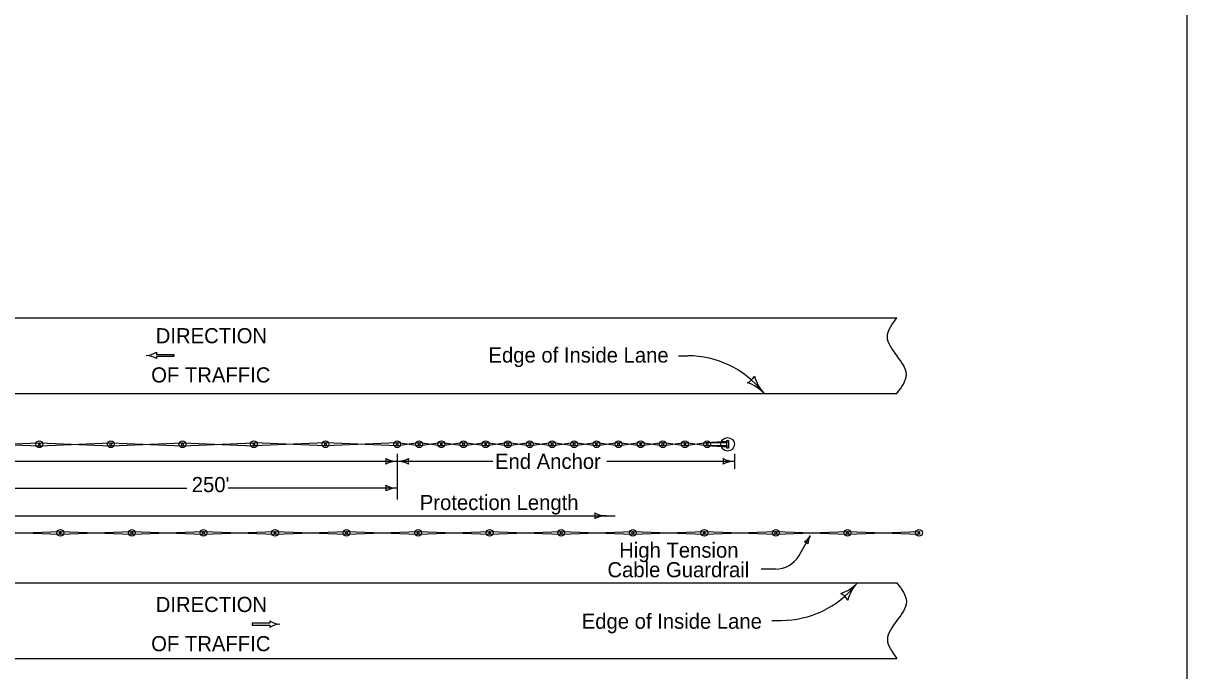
# Model space of a CAD drawing. Extents: x 10133 to 81668, y 7924 to 11018.
# Drawn here: x 12346 to 13268, y 8918 to 9431 of the extents above; entities that cross this region are included whole.
import ezdxf

# ---------------------------------------------------------------- set-up
doc = ezdxf.new("R2010")
doc.units = 0
for name, color, linetype in [('dsnCellElements', 7, 'Continuous'), ('DsnShtRevisedText', 7, 'Continuous'), ('dsnStdDimension', 7, 'Continuous'), ('SheetBorder', 7, 'Continuous')]:
    doc.layers.add(name, color=color, linetype=linetype)

msp = doc.modelspace()

# ---------------------------------------------------------------- linework, layer by layer
at = {"layer": 'dsnCellElements'}
for p, q in [((12302.05, 9098.14), (12357.82, 9095.89)), ((12302.05, 9095.89), (12357.82, 9098.14)), ((12358.76, 9098.14), (12414.52, 9095.89)), ((12358.76, 9095.89), (12414.52, 9098.14)), ((12415.46, 9098.14), (12471.22, 9095.89)), ((12415.46, 9095.89), (12471.22, 9098.14)), ((12472.16, 9098.14), (12527.92, 9095.89)), ((12472.16, 9095.89), (12527.92, 9098.14)), ((12584.62, 9095.89), (12528.86, 9098.14)), ((12584.62, 9098.14), (12528.86, 9095.89)), ((12641.32, 9095.89), (12585.56, 9098.14)), ((12641.32, 9098.14), (12585.56, 9095.89)), ((12658.89, 9095.88), (12642.26, 9098.14)), ((12658.89, 9098.14), (12642.26, 9095.89)), ((12676.41, 9095.89), (12659.83, 9098.14)), ((12676.41, 9098.14), (12659.83, 9095.88)), ((12693.98, 9095.89), (12677.35, 9098.14)), ((12693.98, 9098.14), (12677.35, 9095.89)), ((12711.5, 9095.89), (12694.92, 9098.14)), ((12711.5, 9098.14), (12694.92, 9095.89)), ((12729.07, 9095.89), (12712.44, 9098.14)), ((12729.07, 9098.14), (12712.44, 9095.89)), ((12746.59, 9095.89), (12730.01, 9098.14)), ((12746.59, 9098.14), (12730.01, 9095.89)), ((12764.16, 9095.89), (12747.53, 9098.14)), ((12764.16, 9098.14), (12747.53, 9095.89)), ((12781.68, 9098.14), (12765.1, 9095.89)), ((12781.68, 9095.89), (12765.1, 9098.14)), ((12799.25, 9095.89), (12782.62, 9098.14)), ((12799.25, 9098.14), (12782.62, 9095.89)), ((12816.77, 9095.89), (12800.19, 9098.14)), ((12816.77, 9098.14), (12800.19, 9095.89)), ((12834.35, 9095.89), (12817.72, 9098.14)), ((12834.35, 9098.14), (12817.72, 9095.89)), ((12851.88, 9095.89), (12835.29, 9098.14)), ((12851.88, 9098.14), (12835.29, 9095.89)), ((12869.46, 9095.89), (12852.82, 9098.14)), ((12869.46, 9098.14), (12852.82, 9095.89)), ((12886.98, 9095.89), (12870.39, 9098.14)), ((12886.98, 9098.14), (12870.39, 9095.89)), ((12903.74, 9099.32), (12886.98, 9098.14)), ((12903.74, 9094.71), (12886.98, 9095.89)), ((12903.74, 9098.14), (12887.91, 9098.14)), ((12903.74, 9095.89), (12887.91, 9095.89)), ((12318.73, 9027.97), (12374.49, 9025.72)), ((12318.73, 9025.72), (12374.49, 9027.97)), ((12375.43, 9027.97), (12431.19, 9025.72)), ((12375.43, 9025.72), (12431.19, 9027.97)), ((12432.13, 9027.97), (12487.89, 9025.72)), ((12432.13, 9025.72), (12487.89, 9027.97)), ((12488.83, 9027.97), (12544.59, 9025.72)), ((12488.83, 9025.72), (12544.59, 9027.97)), ((12545.53, 9027.97), (12601.29, 9025.72)), ((12545.53, 9025.72), (12601.29, 9027.97)), ((12602.23, 9027.97), (12658, 9025.72)), ((12602.23, 9025.72), (12658, 9027.97)), ((12658.93, 9027.97), (12714.7, 9025.72)), ((12658.93, 9025.72), (12714.7, 9027.97)), ((12715.64, 9027.97), (12771.4, 9025.72)), ((12715.64, 9025.72), (12771.4, 9027.97)), ((12772.34, 9027.97), (12828.1, 9025.72)), ((12772.34, 9025.72), (12828.1, 9027.97)), ((12829.04, 9027.97), (12884.8, 9025.72)), ((12829.04, 9025.72), (12884.8, 9027.97)), ((12885.74, 9027.97), (12941.5, 9025.72)), ((12885.74, 9025.72), (12941.5, 9027.97)), ((12942.44, 9027.97), (12998.2, 9025.72)), ((12942.44, 9025.72), (12998.2, 9027.97)), ((12999.14, 9027.97), (13054.9, 9025.72)), ((12999.14, 9025.72), (13054.9, 9027.97))]:
    msp.add_line(p, q, dxfattribs=at)
for points in [[(12904.34, 9100.02), (12904.34, 9094.01), (12903.13, 9094.01), (12903.13, 9100.02)], [(12357.82, 9095.89), (12357.82, 9098.14), (12358.76, 9098.14), (12358.76, 9095.89)], [(12357.82, 9095.89), (12357.82, 9098.14), (12358.76, 9098.14), (12358.76, 9095.89)], [(12414.52, 9095.89), (12414.52, 9098.14), (12415.46, 9098.14), (12415.46, 9095.89)], [(12414.52, 9095.89), (12414.52, 9098.14), (12415.46, 9098.14), (12415.46, 9095.89)], [(12471.22, 9095.89), (12471.22, 9098.14), (12472.16, 9098.14), (12472.16, 9095.89)], [(12471.22, 9095.89), (12471.22, 9098.14), (12472.16, 9098.14), (12472.16, 9095.89)], [(12528.86, 9098.14), (12528.86, 9095.89), (12527.92, 9095.89), (12527.92, 9098.14)], [(12527.92, 9095.89), (12527.92, 9098.14), (12528.86, 9098.14), (12528.86, 9095.89)], [(12585.56, 9098.14), (12585.56, 9095.89), (12584.62, 9095.89), (12584.62, 9098.14)], [(12585.56, 9098.14), (12585.56, 9095.89), (12584.62, 9095.89), (12584.62, 9098.14)], [(12642.26, 9098.14), (12642.26, 9095.89), (12641.32, 9095.89), (12641.32, 9098.14)], [(12642.26, 9098.14), (12642.26, 9095.89), (12641.32, 9095.89), (12641.32, 9098.14)], [(12659.83, 9098.14), (12659.83, 9095.88), (12658.89, 9095.88), (12658.89, 9098.14)], [(12677.35, 9098.14), (12677.35, 9095.89), (12676.41, 9095.89), (12676.41, 9098.14)], [(12694.92, 9098.14), (12694.92, 9095.89), (12693.98, 9095.89), (12693.98, 9098.14)], [(12712.44, 9098.14), (12712.44, 9095.89), (12711.5, 9095.89), (12711.5, 9098.14)], [(12730.01, 9098.14), (12730.01, 9095.89), (12729.07, 9095.89), (12729.07, 9098.14)], [(12747.53, 9098.14), (12747.53, 9095.89), (12746.59, 9095.89), (12746.59, 9098.14)], [(12765.1, 9098.14), (12765.1, 9095.89), (12764.16, 9095.89), (12764.16, 9098.14)], [(12782.62, 9098.14), (12782.62, 9095.89), (12781.68, 9095.89), (12781.68, 9098.14)], [(12800.19, 9098.14), (12800.19, 9095.89), (12799.25, 9095.89), (12799.25, 9098.14)], [(12817.71, 9098.14), (12817.71, 9095.89), (12816.77, 9095.89), (12816.77, 9098.14)], [(12835.29, 9098.14), (12835.29, 9095.89), (12834.35, 9095.89), (12834.35, 9098.14)], [(12852.81, 9098.14), (12852.81, 9095.89), (12851.88, 9095.89), (12851.88, 9098.14)], [(12870.39, 9098.14), (12870.39, 9095.89), (12869.46, 9095.89), (12869.46, 9098.14)], [(12887.91, 9098.14), (12887.91, 9095.89), (12886.98, 9095.89), (12886.98, 9098.14)], [(12374.49, 9025.72), (12374.49, 9027.97), (12375.43, 9027.97), (12375.43, 9025.72)], [(12374.49, 9025.72), (12374.49, 9027.97), (12375.43, 9027.97), (12375.43, 9025.72)], [(12431.19, 9025.72), (12431.19, 9027.97), (12432.13, 9027.97), (12432.13, 9025.72)], [(12431.19, 9025.72), (12431.19, 9027.97), (12432.13, 9027.97), (12432.13, 9025.72)], [(12487.89, 9025.72), (12487.89, 9027.97), (12488.83, 9027.97), (12488.83, 9025.72)], [(12487.89, 9025.72), (12487.89, 9027.97), (12488.83, 9027.97), (12488.83, 9025.72)], [(12544.59, 9025.72), (12544.59, 9027.97), (12545.53, 9027.97), (12545.53, 9025.72)], [(12544.59, 9025.72), (12544.59, 9027.97), (12545.53, 9027.97), (12545.53, 9025.72)], [(12601.29, 9025.72), (12601.29, 9027.97), (12602.23, 9027.97), (12602.23, 9025.72)], [(12601.29, 9025.72), (12601.29, 9027.97), (12602.23, 9027.97), (12602.23, 9025.72)], [(12658, 9025.72), (12658, 9027.97), (12658.93, 9027.97), (12658.93, 9025.72)], [(12658, 9025.72), (12658, 9027.97), (12658.93, 9027.97), (12658.93, 9025.72)], [(12714.7, 9025.72), (12714.7, 9027.97), (12715.64, 9027.97), (12715.64, 9025.72)], [(12714.7, 9025.72), (12714.7, 9027.97), (12715.64, 9027.97), (12715.64, 9025.72)], [(12771.4, 9025.72), (12771.4, 9027.97), (12772.34, 9027.97), (12772.34, 9025.72)], [(12771.4, 9025.72), (12771.4, 9027.97), (12772.34, 9027.97), (12772.34, 9025.72)], [(12828.1, 9025.72), (12828.1, 9027.97), (12829.04, 9027.97), (12829.04, 9025.72)], [(12828.1, 9025.72), (12828.1, 9027.97), (12829.04, 9027.97), (12829.04, 9025.72)], [(12884.8, 9025.72), (12884.8, 9027.97), (12885.74, 9027.97), (12885.74, 9025.72)], [(12884.8, 9025.72), (12884.8, 9027.97), (12885.74, 9027.97), (12885.74, 9025.72)], [(12941.5, 9025.72), (12941.5, 9027.97), (12942.44, 9027.97), (12942.44, 9025.72)], [(12941.5, 9025.72), (12941.5, 9027.97), (12942.44, 9027.97), (12942.44, 9025.72)], [(12998.2, 9025.72), (12998.2, 9027.97), (12999.14, 9027.97), (12999.14, 9025.72)], [(12998.2, 9025.72), (12998.2, 9027.97), (12999.14, 9027.97), (12999.14, 9025.72)], [(13054.9, 9025.72), (13054.9, 9027.97), (13055.84, 9027.97), (13055.84, 9025.72)]]:
    msp.add_lwpolyline(points, close=True, dxfattribs=at)
for centre, radius in [((12358.29, 9097.01), 2.66), ((12358.29, 9097.01), 2.66), ((12414.99, 9097.01), 2.66), ((12414.99, 9097.01), 2.66), ((12471.69, 9097.01), 2.66), ((12471.69, 9097.01), 2.66), ((12528.39, 9097.01), 2.66), ((12528.39, 9097.01), 2.66), ((12585.09, 9097.01), 2.66), ((12585.09, 9097.01), 2.66), ((12641.79, 9097.01), 2.66), ((12641.79, 9097.01), 2.66), ((12659.36, 9097.01), 2.66), ((12676.88, 9097.01), 2.66), ((12694.45, 9097.01), 2.66), ((12711.97, 9097.01), 2.66), ((12729.54, 9097.01), 2.66), ((12747.06, 9097.01), 2.66), ((12764.63, 9097.01), 2.66), ((12782.15, 9097.01), 2.66), ((12799.72, 9097.01), 2.66), ((12817.24, 9097.01), 2.66), ((12834.82, 9097.01), 2.66), ((12852.34, 9097.01), 2.66), ((12869.92, 9097.01), 2.66), ((12887.45, 9097.01), 2.66), ((12903.74, 9097.01), 5.4), ((12374.96, 9026.85), 2.66), ((12374.96, 9026.85), 2.66), ((12431.66, 9026.85), 2.66), ((12431.66, 9026.85), 2.66), ((12488.36, 9026.85), 2.66), ((12488.36, 9026.85), 2.66), ((12545.06, 9026.85), 2.66), ((12545.06, 9026.85), 2.66), ((12601.76, 9026.85), 2.66), ((12601.76, 9026.85), 2.66), ((12658.46, 9026.85), 2.66), ((12658.46, 9026.85), 2.66), ((12715.17, 9026.85), 2.66), ((12715.17, 9026.85), 2.66), ((12771.87, 9026.85), 2.66), ((12771.87, 9026.85), 2.66), ((12828.57, 9026.85), 2.66), ((12828.57, 9026.85), 2.66), ((12885.27, 9026.85), 2.66), ((12885.27, 9026.85), 2.66), ((12941.97, 9026.85), 2.66), ((12941.97, 9026.85), 2.66), ((12998.67, 9026.85), 2.66), ((12998.67, 9026.85), 2.66), ((13055.37, 9026.85), 2.66)]:
    msp.add_circle(centre, radius, dxfattribs=at)
at = {"layer": 'DsnShtRevisedText'}
for p, q in [((12442.95, 9167.45), (12442.95, 9167.45)), ((12451.05, 9169.99), (12451.05, 9168.21)), ((12451.05, 9168.21), (12465.02, 9168.21)), ((12465.02, 9166.69), (12451.05, 9166.69)), ((12451.05, 9166.69), (12451.05, 9164.91)), ((12465.02, 9168.21), (12465.02, 9166.69)), ((12864.72, 9167.13), (12872.16, 9167.13)), ((12641.79, 9083.49), (12177.38, 9083.49)), ((12641.79, 9089.49), (12641.79, 9053.27)), ((12717.79, 9083.49), (12641.79, 9083.49)), ((12909.14, 9083.49), (12808.01, 9083.49)), ((12909.14, 9089.49), (12909.14, 9077.49)), ((12318.26, 9062.27), (12475.12, 9062.27)), ((12641.79, 9062.27), (12507.91, 9062.27)), ((12318.26, 9040.37), (12778.6, 9040.37)), ((12778.6, 9040.37), (12814.67, 9040.37)), ((12960.34, 9008.84), (12969.22, 9024.49)), ((12941.54, 8998.04), (12930.29, 8998.04)), ((12540.9, 8955.2), (12526.93, 8955.2)), ((12526.93, 8955.2), (12526.93, 8953.68)), ((12526.93, 8953.68), (12540.9, 8953.68)), ((12540.9, 8956.98), (12540.9, 8955.2)), ((12540.9, 8953.68), (12540.9, 8951.9)), ((12548.99, 8954.44), (12548.99, 8954.44)), ((12938.64, 8957.41), (12946.08, 8957.41))]:
    msp.add_line(p, q, dxfattribs=at)
for centre, radius, start, end in [((12442.28, 9183.81), 16.37, 272.35199, 302.38203), ((12442.28, 9151.09), 16.37, 57.61797, 87.64801), ((12872.16, 9090.94), 76.18, 39.01063, 90), ((12914.17, 9157.13), 12.51, 295.26394, 330.73064), ((12909, 9115.19), 32.38, 42.99729, 71.06977), ((12956.36, 9159.35), 32.38, 194.9248, 222.99729), ((12625.76, 9083.49), 7.39, 342.26665, 17.73335), ((12641.79, 9102.61), 19.13, 241.92751, 270), ((12641.79, 9064.36), 19.13, 90, 118.07249), ((12641.79, 9102.61), 19.13, 270, 298.07249), ((12641.79, 9064.36), 19.13, 61.92751, 90), ((12657.83, 9083.49), 7.39, 162.26665, 197.73335), ((12893.1, 9083.49), 7.39, 342.26665, 17.73335), ((12909.14, 9102.61), 19.13, 241.92751, 270), ((12909.14, 9064.36), 19.13, 90, 118.07249), ((12625.76, 9062.27), 7.39, 342.26665, 17.73335), ((12641.79, 9081.39), 19.13, 241.92751, 270), ((12641.79, 9043.14), 19.13, 90, 118.07249), ((12791.34, 9040.37), 7.39, 342.26665, 17.73335), ((12807.37, 9059.5), 19.13, 241.92751, 270), ((12807.37, 9021.25), 19.13, 90, 118.07249), ((12957.47, 9031.34), 13.6, 301.69616, 329.76864), ((12963.48, 9014.64), 5.25, 42.03529, 77.50199), ((12980.98, 9017.64), 13.6, 149.76864, 177.84113), ((12941.54, 9019.8), 21.76, 270, 329.77566), ((12946.08, 9033.59), 76.18, 270, 320.98937), ((12982.92, 9009.35), 32.38, 288.93023, 317.00271), ((13030.28, 8965.19), 32.38, 137.00271, 165.0752), ((12988.08, 8967.41), 12.51, 29.26936, 64.73606), ((12549.66, 8970.8), 16.37, 237.61797, 267.64801), ((12549.66, 8938.08), 16.37, 92.35199, 122.38203)]:
    msp.add_arc(centre, radius, start, end, dxfattribs=at)
at = {"layer": 'dsnStdDimension'}
for p, q in [((11922.19, 9197.27), (13037.85, 9197.27)), ((11922.19, 9137.27), (13037.85, 9137.27)), ((11922.19, 8987.27), (13037.85, 8987.27)), ((11922.19, 8927.27), (13037.85, 8927.27))]:
    msp.add_line(p, q, dxfattribs=at)
for points in [[(13037.85, 9137.27), (13045.35, 9152.27), (13037.85, 9167.27), (13030.35, 9182.27), (13037.85, 9197.27)], [(13037.85, 8987.27), (13045.35, 8972.27), (13037.85, 8957.27), (13030.35, 8942.27), (13037.85, 8927.27)]]:
    msp.add_spline(points, degree=3, dxfattribs=at)
at = {"layer": 'SheetBorder'}
msp.add_lwpolyline([(10132.52, 9944.02), (13267.53, 9944.02), (13267.53, 7924.02), (10132.52, 7924.02)], close=True, dxfattribs=at)

# ---------------------------------------------------------------- texts
at = {"layer": 'DsnShtRevisedText'}
for s, p in [('DIRECTION', (12450.55, 9177.07)), ('Edge of Inside Lane', (12714.22, 9161.77)), ('OF TRAFFIC', (12446.94, 9146.01)), ('End Anchor', (12719.39, 9077.49)), ("250'", (12479.1, 9059.07)), ('Protection Length', (12659.8, 9044.89)), ('High Tension', (12817.79, 9007.13)), ('Cable Guardrail', (12808.5, 8991.6)), ('DIRECTION', (12450.55, 8964.06)), ('Edge of Inside Lane', (12788.13, 8950.77)), ('OF TRAFFIC', (12446.94, 8933))]:
    msp.add_text(s, height=12, dxfattribs=at).set_placement(p)

doc.saveas('drawing.dxf')
